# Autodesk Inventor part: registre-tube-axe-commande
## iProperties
Author: chr
Created: 2001-06
Part Number: registre-tube-axe-commande
Material: Par défaut
Document SubType Name: Modélisation
Designer: chr
Control State: 0
Master: False
Checked Out: False
PropertySet Name: Design Tracking Control
Shininess: 21.0
PropertySet Name: _Private Model Information
Length Units: 11269
Angle Units: 11286
Time Units: 11279
Mass Units: 11290
Length Display Precision: 3
Angle Display Precision: 2
Compacted: False
Density: 0.0
Volumn: 0.0
Area: 0.0
PropertySet Name: Model Information
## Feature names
1. Extrusion1
2. Extrusion2
